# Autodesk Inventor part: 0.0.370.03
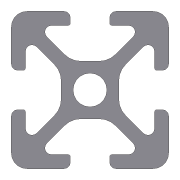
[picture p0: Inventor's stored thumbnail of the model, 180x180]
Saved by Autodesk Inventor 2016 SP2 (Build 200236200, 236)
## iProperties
Category: natur
Company: CAD Team Handzik
Created: 2017-10
Part Number: 0.0.370.03
Document SubType Name: Modeling
Designer: CAD Team Handzik
Density: 2.71 g/cm^3
Material: Aluminium - 6061
Appearance: Aluminium - flach
Vendor: Item
MT_KOPF: =<CPR_ZEICHNR> - <CPR_SHORT>
LANG: 100,000 mm
Author: CAD Team Handzik
Title: Profil 5 20x20
Subject: Muster für iPart Modul
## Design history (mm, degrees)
node "Startebene"
node "Endebene"
sketch "Skizze1"
  geometry: L1 (4.7, 0)-(0, 0) reference; L2 (-0.8, 1.5)-(-0.8, 0.8) reference; L3 (1.618, 1.8)-(-0.5, 1.8) reference; L4 (6.7, 6.7)-(6.7, 2) reference; L5 (5.9, 7.5)-(5.2, 7.5) reference; L6 (4.9, 7.2)-(4.9, 5.082) reference; L7 (-0.044, 5.471)-(2.206, 3.221) reference; L8 (3.479, 4.494)-(1.229, 6.744) reference; L9 (4.9, 14.918)-(4.9, 12.8) reference; L10 (5.2, 12.5)-(5.9, 12.5) reference; L11 (6.7, 18)-(6.7, 13.3) reference; L12 (2.206, 16.779)-(-0.044, 14.529) reference; L13 (0, 20)-(4.7, 20) reference; L14 (-0.5, 18.2)-(1.618, 18.2) reference; L15 (-0.8, 19.2)-(-0.8, 18.5) reference; L16 (-11.5, 12.8)-(-11.5, 14.918) reference; L17 (-10.079, 15.506)-(-7.829, 13.256) reference; L18 (-13.3, 13.3)-(-13.3, 18) reference; L19 (-6.556, 14.529)-(-8.806, 16.779) reference; L20 (-11.3, 20)-(-6.6, 20) reference; L21 (-5.8, 18.5)-(-5.8, 19.2) reference; L22 (-8.218, 18.2)-(-6.1, 18.2) reference; L23 (-12.5, 12.5)-(-11.8, 12.5) reference; L24 (-4.435, 6.35)-(-2.165, 6.35) reference; L25 (-5.8, 0.8)-(-5.8, 1.5) reference; L26 (-6.1, 1.8)-(-8.218, 1.8) reference; L27 (-6.95, 11.135)-(-6.95, 8.865) reference; L28 (-11.8, 7.5)-(-12.5, 7.5) reference; L29 (-11.5, 5.082)-(-11.5, 7.2) reference; L30 (-7.829, 6.744)-(-10.079, 4.494) reference; L31 (-13.3, 2)-(-13.3, 6.7) reference; L32 (-8.806, 3.221)-(-6.556, 5.471) reference; L33 (-6.6, 0)-(-11.3, 0) reference; L34 (-2.165, 13.65)-(-4.435, 13.65) reference; L35 (0.35, 8.865)-(0.35, 11.135) reference; L36 (1.229, 13.256)-(3.479, 15.506) reference; C1 r 2.15 at (-3.3, 10) reference; A1 r 2 centre (4.7, 2) between (4.7, 0) and (6.7, 2) reference; A2 r 0.832 centre (4.068, 5.082) between (3.479, 4.494) and (4.9, 5.082) reference; A3 r 0.832 centre (1.618, 2.632) between (1.618, 1.8) and (2.206, 3.221) reference; A4 r 0.8 centre (0, 0.8) between (-0.8, 0.8) and (0, 0) reference; A5 r 0.3 centre (-0.5, 1.5) between (-0.5, 1.8) and (-0.8, 1.5) reference; A6 r 0.8 centre (5.9, 6.7) between (6.7, 6.7) and (5.9, 7.5) reference; A7 r 0.3 centre (5.2, 7.2) between (5.2, 7.5) and (4.9, 7.2) reference; A8 r 0.3 centre (5.2, 12.8) between (4.9, 12.8) and (5.2, 12.5) reference; A9 r 0.8 centre (5.9, 13.3) between (5.9, 12.5) and (6.7, 13.3) reference; A10 r 0.832 centre (4.068, 14.918) between (4.9, 14.918) and (3.479, 15.506) reference; A11 r 2 centre (4.7, 18) between (6.7, 18) and (4.7, 20) reference; A12 r 0.832 centre (1.618, 17.368) between (2.206, 16.779) and (1.618, 18.2) reference; A13 r 0.3 centre (-0.5, 18.5) between (-0.8, 18.5) and (-0.5, 18.2) reference; A14 r 0.8 centre (0, 19.2) between (0, 20) and (-0.8, 19.2) reference; A15 r 0.832 centre (-10.668, 14.918) between (-10.079, 15.506) and (-11.5, 14.918) reference; A16 r 3 centre (-4.435, 16.65) between (-6.556, 14.529) and (-4.435, 13.65) reference; A17 r 2 centre (-11.3, 18) between (-11.3, 20) and (-13.3, 18) reference; A18 r 0.832 centre (-8.218, 17.368) between (-8.218, 18.2) and (-8.806, 16.779) reference; A19 r 0.3 centre (-6.1, 18.5) between (-6.1, 18.2) and (-5.8, 18.5) reference; A20 r 0.8 centre (-6.6, 19.2) between (-5.8, 19.2) and (-6.6, 20) reference; A21 r 3 centre (-9.95, 11.135) between (-6.95, 11.135) and (-7.829, 13.256) reference; A22 r 0.3 centre (-11.8, 12.8) between (-11.8, 12.5) and (-11.5, 12.8) reference; A23 r 0.8 centre (-12.5, 13.3) between (-13.3, 13.3) and (-12.5, 12.5) reference; A24 r 0.8 centre (-6.6, 0.8) between (-6.6, 0) and (-5.8, 0.8) reference; A25 r 0.3 centre (-6.1, 1.5) between (-5.8, 1.5) and (-6.1, 1.8) reference; A26 r 3 centre (-4.435, 3.35) between (-4.435, 6.35) and (-6.556, 5.471) reference; A27 r 3 centre (-9.95, 8.865) between (-7.829, 6.744) and (-6.95, 8.865) reference; A28 r 0.3 centre (-11.8, 7.2) between (-11.5, 7.2) and (-11.8, 7.5) reference; A29 r 0.8 centre (-12.5, 6.7) between (-12.5, 7.5) and (-13.3, 6.7) reference; A30 r 0.832 centre (-10.668, 5.082) between (-11.5, 5.082) and (-10.079, 4.494) reference; A31 r 0.832 centre (-8.218, 2.632) between (-8.806, 3.221) and (-8.218, 1.8) reference; A32 r 2 centre (-11.3, 2) between (-13.3, 2) and (-11.3, 0) reference; A33 r 3 centre (3.35, 8.865) between (0.35, 8.865) and (1.229, 6.744) reference; A34 r 3 centre (-2.165, 3.35) between (-0.044, 5.471) and (-2.165, 6.35) reference; A35 r 3 centre (-2.165, 16.65) between (-2.165, 13.65) and (-0.044, 14.529) reference; A36 r 3 centre (3.35, 11.135) between (1.229, 13.256) and (0.35, 11.135) reference
  constraints: 72 end point, 72 point on circle, 37 centre point, 14 horizontal, 14 vertical, 154 other
extrude "Extrusion4" new body sketch "Skizze1" stored distance "d10" = 10; taper "d11" = 0 deg
node "Volumenkörper3"
node "Volumenkörper"
node "Flächenkörper"
other parameters: "LANG" = 100 [user parameter; used in 2 equation terms]
